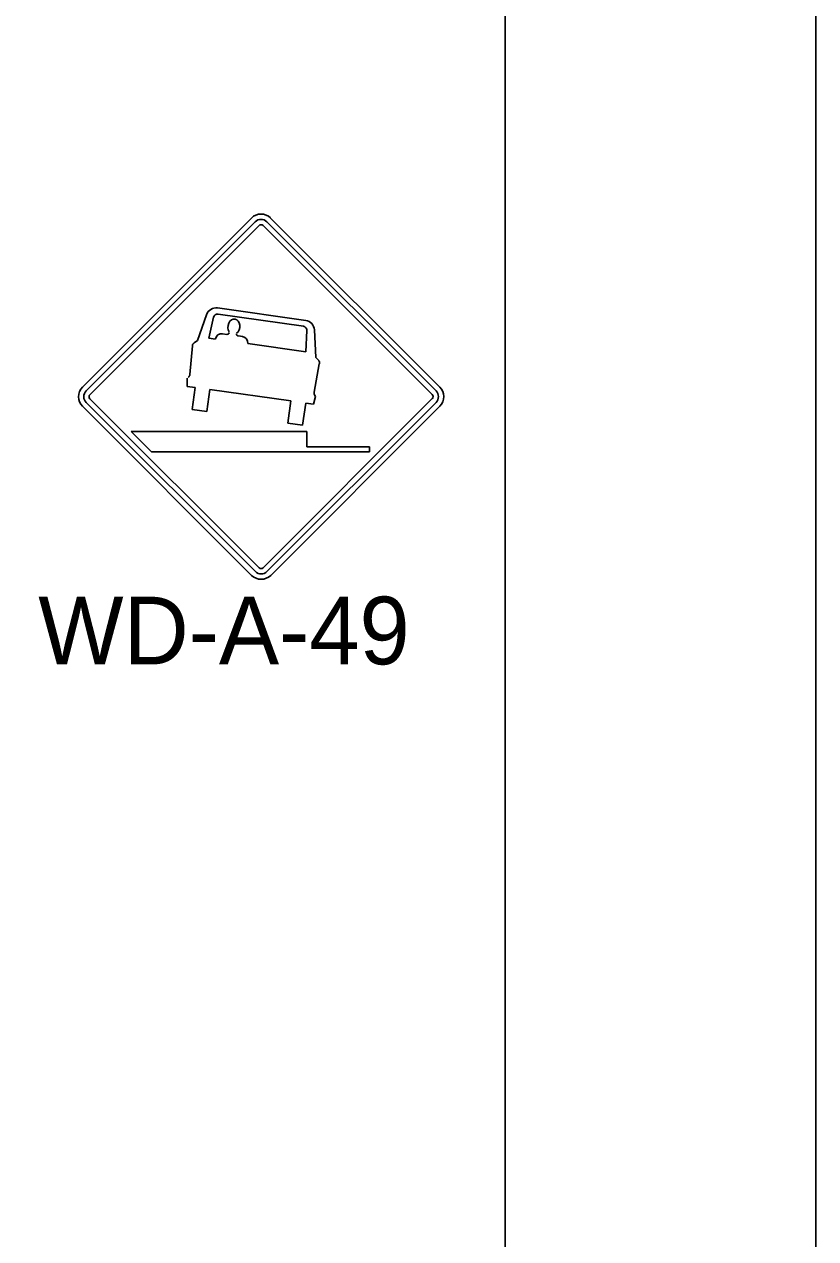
# Model space of a CAD drawing. Extents: x 2195 to 2411, y 202 to 481.
# Drawn here: x 2385.9 to 2411.4, y 323.97 to 363.08 of the extents above; entities that cross this region are included whole.
import ezdxf

# ---------------------------------------------------------------- set-up
doc = ezdxf.new("R2010")
doc.units = 0
for name, color, linetype in [('Level 1', 7, 'Continuous'), ('Level 10', 7, 'Continuous'), ('Level 60', 7, 'Continuous')]:
    doc.layers.add(name, color=color, linetype=linetype)

msp = doc.modelspace()

# ---------------------------------------------------------------- linework, layer by layer
at = {"layer": 'Level 1'}
for p, q in [((2387.777, 351.392), (2393.223, 356.839)), ((2387.777, 351.392), (2393.223, 356.839)), ((2387.898, 351.271), (2393.345, 356.718)), ((2393.718, 356.718), (2399.168, 351.274)), ((2393.839, 356.839), (2399.289, 351.396)), ((2388.019, 351.15), (2393.466, 356.596)), ((2393.597, 356.596), (2399.047, 351.153)), ((2392.125, 353.948), (2394.971, 353.537)), ((2391.482, 352.895), (2391.774, 353.722)), ((2391.853, 352.974), (2391.999, 353.643)), ((2392.151, 353.742), (2394.899, 353.352)), ((2392.29, 353.113), (2392.288, 353.112)), ((2392.429, 353.093), (2392.29, 353.113)), ((2395.004, 353.213), (2394.971, 352.531)), ((2395.249, 353.239), (2395.296, 352.352)), ((2391.237, 351.803), (2391.323, 352.723)), ((2391.376, 352.822), (2391.482, 352.895)), ((2392.065, 352.941), (2391.853, 352.974)), ((2392.939, 353.021), (2392.793, 353.041)), ((2394.971, 352.531), (2393.104, 352.796)), ((2395.296, 352.352), (2395.388, 352.253)), ((2395.408, 352.147), (2395.243, 351.227)), ((2391.151, 351.419), (2391.151, 351.683)), ((2391.409, 351.385), (2391.151, 351.419)), ((2391.31, 350.67), (2391.409, 351.385)), ((2391.886, 351.319), (2391.787, 350.604)), ((2394.495, 350.948), (2391.886, 351.319)), ((2393.227, 345.333), (2387.777, 350.776)), ((2393.227, 345.333), (2387.777, 350.776)), ((2393.348, 345.454), (2387.898, 350.897)), ((2393.469, 345.575), (2388.019, 351.019)), ((2393.329, 350.993), (2393.329, 350.993)), ((2399.047, 351.022), (2393.6, 345.575)), ((2399.168, 350.901), (2393.721, 345.454)), ((2399.289, 350.779), (2393.843, 345.333)), ((2394.389, 350.233), (2394.495, 350.948)), ((2394.971, 350.882), (2394.865, 350.167)), ((2395.216, 350.849), (2394.971, 350.876)), ((2395.283, 351.094), (2395.216, 350.849)), ((2395.263, 351.127), (2395.283, 351.094)), ((2391.787, 350.604), (2391.31, 350.67)), ((2394.865, 350.167), (2394.389, 350.233)), ((2390.006, 349.307), (2389.344, 349.969)), ((2389.344, 349.969), (2395.004, 349.969)), ((2395.004, 349.969), (2395.004, 349.472)), ((2397.03, 349.307), (2390.006, 349.307)), ((2395.004, 349.472), (2397.03, 349.472)), ((2397.03, 349.472), (2397.03, 349.307))]:
    msp.add_line(p, q, dxfattribs=at)
for centre, radius, start, end in [((2393.531, 356.531), 0.436, 45.0349, 135), ((2393.531, 356.531), 0.436, 45.0349, 135), ((2393.531, 356.531), 0.264, 45.0349, 135), ((2393.531, 356.531), 0.0926, 45.0349, 135), ((2392.083, 353.618), 0.328, 81.9388, 160.7571), ((2392.131, 353.611), 0.131, 81.9344, 167.2438), ((2394.924, 353.216), 0.328, 3.1113, 81.9386), ((2392.26, 352.917), 0.197, 81.9281, 171.9074), ((2392.44, 353.157), 0.0655, 261.9205, 351.8582), ((2392.803, 353.105), 0.0655, 171.8828, 261.9459), ((2394.877, 353.222), 0.131, 356.6105, 81.9338), ((2391.451, 352.712), 0.131, 124.8259, 174.8703), ((2392.909, 352.825), 0.197, 351.9552, 81.9216), ((2395.282, 352.169), 0.131, 349.4832, 39.2839), ((2391.107, 351.813), 0.131, 304.1825, 354.8723), ((2388.084, 351.084), 0.436, 135, 225.0349), ((2388.084, 351.084), 0.264, 135, 225.0349), ((2395.369, 351.203), 0.131, 169.4858, 215.1975), ((2398.981, 351.087), 0.0926, 315, 45.035), ((2398.981, 351.087), 0.264, 315, 45.035), ((2398.981, 351.087), 0.436, 315, 45.035), ((2388.084, 351.084), 0.0926, 135, 225.0349), ((2393.535, 345.641), 0.436, 225.0348, 315), ((2393.535, 345.641), 0.436, 225.0348, 315), ((2393.535, 345.641), 0.264, 225.0348, 315), ((2393.535, 345.641), 0.0926, 225.0348, 315)]:
    msp.add_arc(centre, radius, start, end, dxfattribs=at)
msp.add_ellipse((2392.655, 353.343), major_axis=(-0.033, -0.243), ratio=0.783636, start_param=0.628057, end_param=5.591652, dxfattribs=at)
at = {"layer": 'Level 60'}
for points in [[(2195.401, 480.884), (2411.401, 480.884), (2411.401, 201.884), (2195.401, 201.884)], [(2214.527, 470.075), (2401.401, 470.075), (2401.401, 212.693), (2214.527, 212.693)]]:
    msp.add_lwpolyline(points, close=True, dxfattribs=at)

# ---------------------------------------------------------------- texts
at = {"layer": 'Level 10'}
msp.add_text('WD-A-49', height=2.177, rotation=360, dxfattribs=at).set_placement((2386.353, 342.468))

doc.saveas('drawing.dxf')
